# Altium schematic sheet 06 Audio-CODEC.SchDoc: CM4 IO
size 297 x 209 mm; Page Create Date: March  8, 1995; Page Number: 6; Page Size: A4; Comment: radxa_1010; Page Count: 19; RevCode: V1.10; Doc: 06 Audio-CODEC; DsnPath: D:\WMS\黄工\[RC126]CM4_IO_V1.10\[RC126]_V1.10\CM4 IO_V1.10.DSN; SchematicName: CM4 IO V1.10; PageName: 06 Audio-CODEC; PageSize: A4; TopSchematic: True
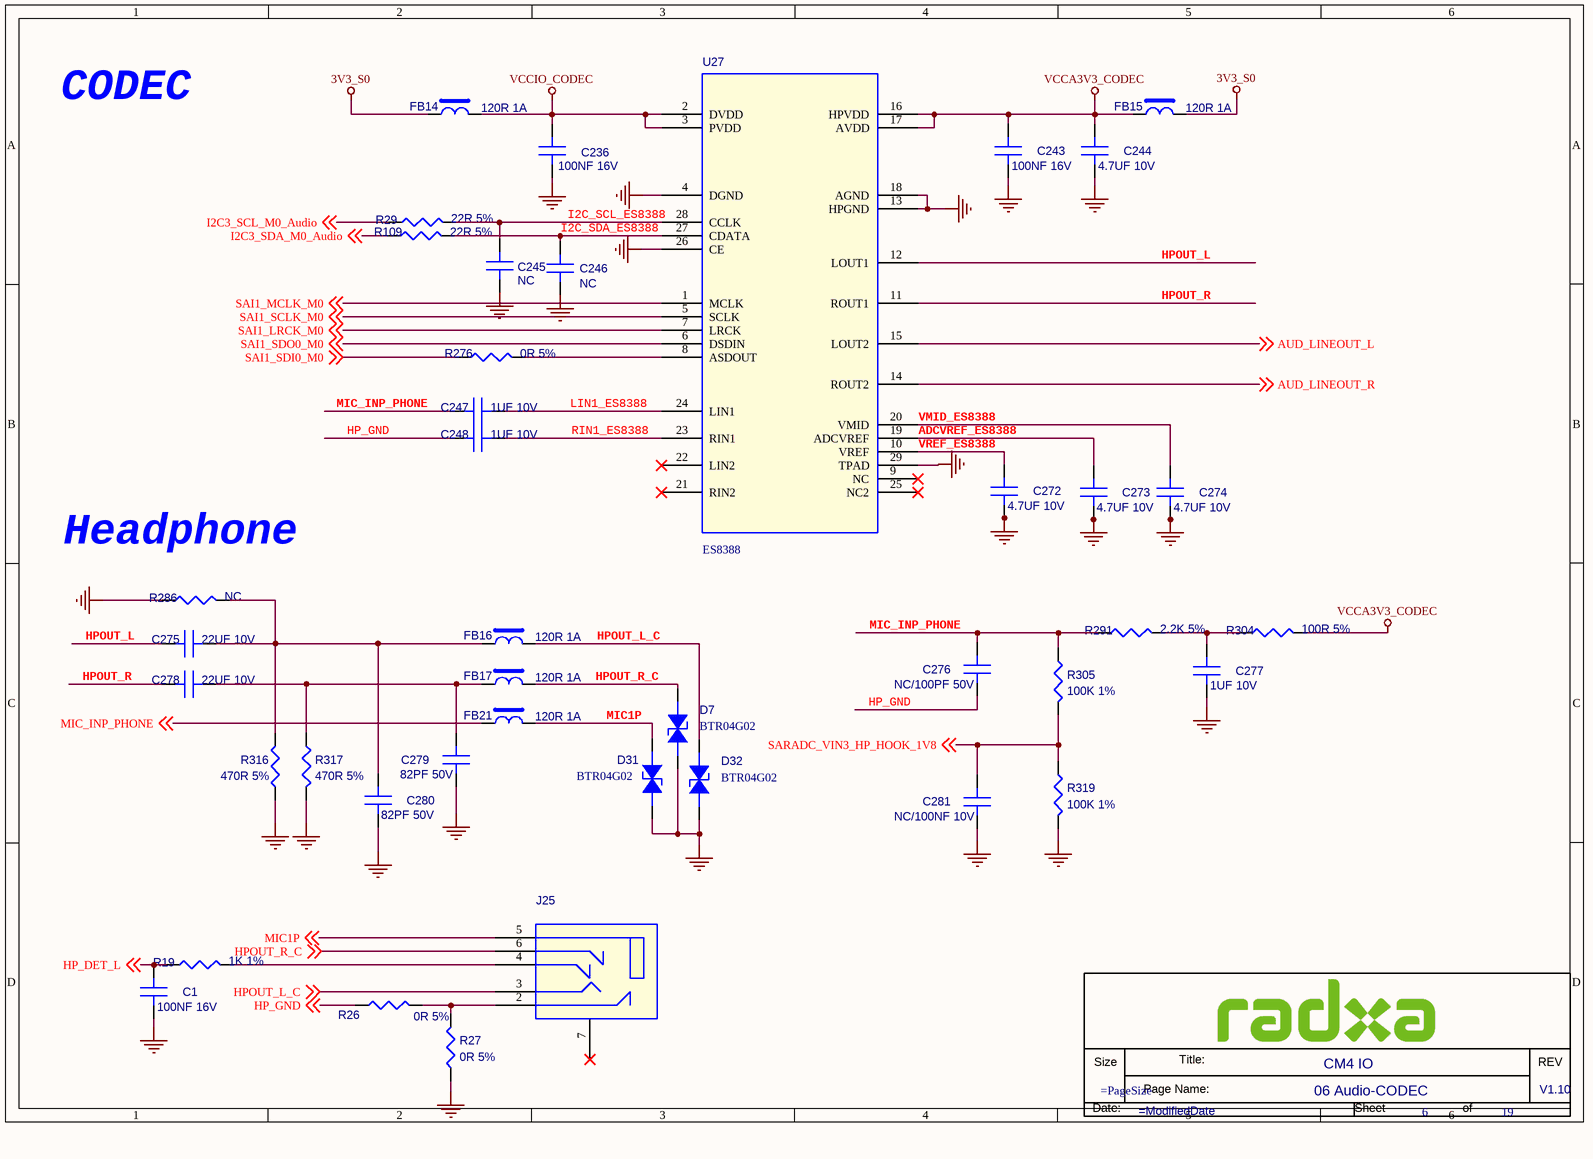
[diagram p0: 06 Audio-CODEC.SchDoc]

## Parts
*  Doc: 06 Audio-CODEC  RevCode: V1.10  Title: CM4 IO  Page Number: 6  Page Count: 19  (hidden comment: radxa_1010)  (graphical)
C1  100NF 16V  [C0201]
C236  100NF 16V  [C0201]
C243  100NF 16V  [C0201]
C244  4.7UF 10V  [C0402]
C245  NC  [C0201]
C246  NC  [C0201]
C247  1UF 10V  [C0201]
C248  1UF 10V  [C0201]
C272  4.7UF 10V  [C0402]
C273  4.7UF 10V  [C0402]
C274  4.7UF 10V  [C0402]
C275  22UF 10V  [C0603]
C276  NC/100PF 50V  [C0201]
C277  1UF 10V  [C0201]
C278  22UF 10V  [C0603]
C279  82PF 50V  [C0201]
C280  82PF 50V  [C0201]
C281  NC/100NF 10V  [C0201]
D7  BTR04G02  [DFN1006-2L]
D31  BTR04G02  [DFN1006-2L]
D32  BTR04G02  [DFN1006-2L]
FB14  120R 1A  [FB0201]
FB15  120R 1A  [FB0201]
FB16  120R 1A  [FB0201]
FB17  120R 1A  [FB0201]
FB21  120R 1A  [FB0201]
J25  (no value)  [AUDIO_SM6_LIE]
R19  1K 1%  [R0402]
R26  0R 5%  [R0402]
R27  0R 5%  [R0402]
R29  22R 5%  [R0402]
R109  22R 5%  [R0402]
R276  0R 5%  [R0402]
R286  NC  [R0402]
R291  2.2K 5%  [R0402]
R304  100R 5%  [R0402]
R305  100K 1%  [R0402]
R316  470R 5%  [R0402]
R317  470R 5%  [R0402]
R319  100K 1%  [R0402]
U27  ES8388  [QFN28_4X4]

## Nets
3V3_S0: FB14.1 FB15.1
GND: C1.2(B) C236.2(B) C243.2(B) C244.2(B) C245.2(B) C246.2(B) C272.2(B) C273.2(B) C274.2(B) C277.2(B) C279.2(B) C280.2(B) C281.2(B) D7.2(CATHODE) D31.2(CATHODE) D32.2(CATHODE) R27.1 R286.1 R316.2 R317.2 R319.2 U27.4(DGND) U27.13(HPGND) U27.18(AGND) U27.26(CE) U27.29(TPAD)
VCCA3V3_CODEC: C243.1(A) C244.1(A) FB15.2 R304.2 U27.16(HPVDD) U27.17(AVDD)
VCCIO_CODEC: C236.1(A) FB14.2 U27.2(DVDD) U27.3(PVDD)
ADCVREF_ES8388: C273.1(A) U27.19(ADCVREF)
AUD_LINEOUT_L: U27.15(LOUT2) ; off-sheet AUD_LINEOUT_L
AUD_LINEOUT_R: U27.14(ROUT2) ; off-sheet AUD_LINEOUT_R
HP_DET_L: C1.1(A) R19.1 ; off-sheet HP_DET_L
HP_GND: C248.2(B) C276.2(B) R26.1 ; off-sheet HP_GND
HPOUT_L: C275.1(A) U27.12(LOUT1)
HPOUT_L_C: D32.1(ANODE) FB16.2 J25.3(R) ; off-sheet HPOUT_L_C
HPOUT_R: C278.1(A) U27.11(ROUT1)
HPOUT_R_C: D7.1(ANODE) FB17.2 J25.6(HP) ; off-sheet HPOUT_R_C
I2C3_SCL_M0_Audio: R29.1 ; off-sheet I2C3_SCL_M0_Audio
I2C3_SDA_M0_Audio: R109.1 ; off-sheet I2C3_SDA_M0_Audio
I2C_SCL_ES8388: C245.1(A) R29.2 U27.28(CCLK)
I2C_SDA_ES8388: C246.1(A) R109.2 U27.27(CDATA)
LIN1_ES8388: C247.1(A) U27.24(LIN1)
MIC1P: D31.1(ANODE) FB21.2 J25.5(D) ; off-sheet MIC1P
MIC_INP_PHONE: C247.2(B) C276.1(A) FB21.1 R291.1 R305.1 ; off-sheet MIC_INP_PHONE
RIN1_ES8388: C248.1(A) U27.23(RIN1)
SAI1_LRCK_M0: U27.7(LRCK) ; off-sheet SAI1_LRCK_M0
SAI1_MCLK_M0: U27.1(MCLK) ; off-sheet SAI1_MCLK_M0
SAI1_SCLK_M0: U27.5(SCLK) ; off-sheet SAI1_SCLK_M0
SAI1_SDI0_M0: R276.1 ; off-sheet SAI1_SDI0_M0
SAI1_SDO0_M0: U27.6(DSDIN) ; off-sheet SAI1_SDO0_M0
SARADC_VIN3_HP_HOOK_1V8: C281.1(A) R305.2 R319.1 ; off-sheet SARADC_VIN3_HP_HOOK_1V8
VMID_ES8388: C274.1(A) U27.20(VMID)
VREF_ES8388: C272.1(A) U27.10(VREF)
NetC275_2: C275.2(B) C280.1(A) FB16.1 R286.2 R316.1
NetC277_1: C277.1(A) R291.2 R304.1
NetC278_2: C278.2(B) C279.1(A) FB17.1 R317.1
NetJ25_2: J25.2(DH) R26.2 R27.2
NetJ25_4: J25.4(L) R19.2
NetR276_2: R276.2 U27.8(ASDOUT)

Not connected (* = marked no-connect by the designer): J25 7(NC2)*; U27 9(NC)* 21(RIN2)* 22(LIN2)* 25(NC2)*

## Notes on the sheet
- CODEC
- (near R286) Headphone

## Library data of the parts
C1 = C: SMD  0201  100NF  16V  X5R  ±20%  ROHS; PARTS: 1; Part Reference: C1; Part Number: A1C01.00099; OriginalSymbolOrigin: (0,30); PKG_TYPE: CAP2-100-250; LEVEL: STD; PINSWAP: (A,B); Preferred: 6715f349cd0bc5
C236 = C: SMD  0201  100NF  16V  X5R  ±20%  ROHS; PARTS: 1; Part Reference: C236; Part Number: A1C01.00099; OriginalSymbolOrigin: (0,30); PKG_TYPE: CAP2-100-250; LEVEL: STD; PINSWAP: (A,B); Preferred: 6715f349cd0bc5
C243 = C: SMD  0201  100NF  16V  X5R  ±20%  ROHS; PARTS: 1; Part Reference: C243; Part Number: A1C01.00099; OriginalSymbolOrigin: (0,30); PKG_TYPE: CAP2-100-250; LEVEL: STD; PINSWAP: (A,B); Preferred: 6715f349cd0bc5
C244 = C: SMD  0402  4.7UF  10V  X5R  ±20%  ROHS; PARTS: 1; Part Reference: C244; Part Number: A1C01.00073; OriginalSymbolOrigin: (0,30); PKG_TYPE: CAP2-100-250; LEVEL: STD; PINSWAP: (A,B)
C245 = C: SMD  0201  10PF  50V  NPO  ±5%  ROHS; PARTS: 1; Part Reference: C245; Part Number: A1C01.00141; OriginalSymbolOrigin: (0,30); PKG_TYPE: CAP2-100-250; LEVEL: STD; PINSWAP: (A,B)
C246 = C: SMD  0201  10PF  50V  NPO  ±5%  ROHS; PARTS: 1; Part Reference: C246; Part Number: A1C01.00141; OriginalSymbolOrigin: (0,30); PKG_TYPE: CAP2-100-250; LEVEL: STD; PINSWAP: (A,B)
C247 = C: SMD  0201  1UF  10V  X5R  ±20%  ROHS; PARTS: 1; Part Reference: C247; Part Number: A1C01.00081; OriginalSymbolOrigin: (0,30); PKG_TYPE: CAP2-100-250; LEVEL: STD; PINSWAP: (A,B)
C248 = C: SMD  0201  1UF  10V  X5R  ±20%  ROHS; PARTS: 1; Part Reference: C248; Part Number: A1C01.00081; OriginalSymbolOrigin: (0,30); PKG_TYPE: CAP2-100-250; LEVEL: STD; PINSWAP: (A,B)
C272 = C: SMD  0402  4.7UF  10V  X5R  ±20%  ROHS; PARTS: 1; Part Reference: C272; Part Number: A1C01.00073; OriginalSymbolOrigin: (0,30); PKG_TYPE: CAP2-100-250; LEVEL: STD; PINSWAP: (A,B)
C273 = C: SMD  0402  4.7UF  10V  X5R  ±20%  ROHS; PARTS: 1; Part Reference: C273; Part Number: A1C01.00073; OriginalSymbolOrigin: (0,30); PKG_TYPE: CAP2-100-250; LEVEL: STD; PINSWAP: (A,B)
C274 = C: SMD  0402  4.7UF  10V  X5R  ±20%  ROHS; PARTS: 1; Part Reference: C274; Part Number: A1C01.00073; OriginalSymbolOrigin: (0,30); PKG_TYPE: CAP2-100-250; LEVEL: STD; PINSWAP: (A,B)
C275 = C: SMD  0603  22UF  10V  X5R  ±20%  ROHS; PARTS: 1; Part Reference: C275; Part Number: A1C01.00015; OriginalSymbolOrigin: (0,30); PKG_TYPE: CAP2-100-250; LEVEL: STD; PINSWAP: (A,B); Preferred: 6715f349cd0bc5
C276 = C: SMD  0201  100PF  50V  NPO  ±5%  ROHS; PARTS: 1; Part Reference: C276; Part Number: A1C01.00382; OriginalSymbolOrigin: (0,30); PKG_TYPE: CAP2-100-250; LEVEL: STD; PINSWAP: (A,B)
C277 = C: SMD  0201  1UF  10V  X5R  ±20%  ROHS; PARTS: 1; Part Reference: C277; Part Number: A1C01.00081; OriginalSymbolOrigin: (0,30); PKG_TYPE: CAP2-100-250; LEVEL: STD; PINSWAP: (A,B)
C278 = C: SMD  0603  22UF  10V  X5R  ±20%  ROHS; PARTS: 1; Part Reference: C278; Part Number: A1C01.00015; OriginalSymbolOrigin: (0,30); PKG_TYPE: CAP2-100-250; LEVEL: STD; PINSWAP: (A,B); Preferred: 6715f349cd0bc5
C279 = C: SMD  0201  82PF  50V  COG  ±2%  ROHS; PARTS: 1; Part Reference: C279; Part Number: A1C01.00327; OriginalSymbolOrigin: (0,30); PKG_TYPE: CAP2-100-250; LEVEL: STD; PINSWAP: (A,B)
C280 = C: SMD  0201  82PF  50V  COG  ±2%  ROHS; PARTS: 1; Part Reference: C280; Part Number: A1C01.00327; OriginalSymbolOrigin: (0,30); PKG_TYPE: CAP2-100-250; LEVEL: STD; PINSWAP: (A,B)
C281 = C: SMD  0201  100NF  10V  X5R  ±20%  ROHS; PARTS: 1; Part Reference: C281; Part Number: A1C01.00009; OriginalSymbolOrigin: (0,30); PKG_TYPE: CAP2-100-250; LEVEL: STD; PINSWAP: (A,B)
D7 = ESD: SMD  编带  0402  BTR04G02  B-tron  ROHS; Part Reference: D7; Part Number: A1D02.00002; Parameter: ESD-台舟 ESD5341N-封装 esd0402; ID: DE-E0004; PCB Footprint: ESD_D0402; Temp Coeff: -50℃ ~ +125℃
D31 = ESD: SMD  编带  0402  BTR04G02  B-tron  ROHS; Part Reference: D31; Part Number: A1D02.00002; Parameter: ESD-台舟 ESD5341N-封装 esd0402; ID: DE-E0004; PCB Footprint: ESD_D0402; Temp Coeff: -50℃ ~ +125℃
D32 = ESD: SMD  编带  0402  BTR04G02  B-tron  ROHS; Part Reference: D32; Part Number: A1D02.00002; Parameter: ESD-台舟 ESD5341N-封装 esd0402; ID: DE-E0004; PCB Footprint: ESD_D0402; Temp Coeff: -50℃ ~ +125℃
FB14 = BEAD: SMD  0201  FB120R  1A  MPZ0603S121HT000  ±25%  ROHS; Part Reference: FB14; Part Number: A1L09.00033
FB15 = BEAD: SMD  0201  FB120R  1A  MPZ0603S121HT000  ±25%  ROHS; Part Reference: FB15; Part Number: A1L09.00033
FB16 = BEAD: SMD  0201  FB120R  1A  MPZ0603S121HT000  ±25%  ROHS; Part Reference: FB16; Part Number: A1L09.00033
FB17 = BEAD: SMD  0201  FB120R  1A  MPZ0603S121HT000  ±25%  ROHS; Part Reference: FB17; Part Number: A1L09.00033
FB21 = BEAD: SMD  0201  FB120R  1A  MPZ0603S121HT000  ±25%  ROHS; Part Reference: FB21; Part Number: A1L09.00033
J25 = PJ342B: SMD  XJ-DR-PJ342B-00  6PIN  外孔Φ6.0mm  内孔Φ3.6mm  前插后贴  14*6.4*H4.5MM  黑色  镀金铜头   协佳  ROHS; Part Reference: J25; Part Number: A1J10.00001
R19 = R: SMD  0201  1K  1/20W  ±1%  ROHS; Part Reference: R19; Part Number: A1R01.00111; PCB Footprint: R0201; Preferred: 6715f349cd0bc5
R26 = R: SMD  0201  0R  1/20W  ±5%  ROHS; Part Reference: R26; Part Number: A1R01.00027; PCB Footprint: R0201; Temp Coeff: －55℃ ~ ＋125℃
R27 = R: SMD  0201  0R  1/20W  ±5%  ROHS; Part Reference: R27; Part Number: A1R01.00027; PCB Footprint: R0201; Temp Coeff: －55℃ ~ ＋125℃
R29 = R: SMD  0201  22R  1/20W  ±5%  ROHS; Part Reference: R29; Part Number: A1R01.00024; PCB Footprint: R0201
R109 = R: SMD  0201  22R  1/20W  ±5%  ROHS; Part Reference: R109; Part Number: A1R01.00024; PCB Footprint: R0201
R276 = R: SMD  0201  0R  1/20W  ±5%  ROHS; Part Reference: R276; Part Number: A1R01.00027; PCB Footprint: R0201; Temp Coeff: －55℃ ~ ＋125℃
R286 = R: SMD  0201  10K  1/20W  ±5%  ROHS; Part Reference: R286; Part Number: A1R01.00012; PCB Footprint: R0201; Temp Coeff: －55℃ ~ ＋125℃
R291 = R: SMD  0201  2.2K  1/20W  ±5%  ROHS; Part Reference: R291; Part Number: A1R01.00016; PCB Footprint: R0201; Temp Coeff: －55℃ ~ ＋125℃
R304 = R: SMD  0201  100R  1/20W  ±5%  ROHS; Part Reference: R304; Part Number: A1R01.00023; PCB Footprint: R0201; Temp Coeff: －55℃ ~ ＋125℃
R305 = R: SMD  0201  100K  1/20W  ±1%  ROHS; Part Reference: R305; Part Number: A1R01.00165; Preferred: 6715f349cd0bc5
R316 = R: SMD  0201  470R  1/20W  ±5%  ROHS; Part Reference: R316; Part Number: A1R01.00020; PCB Footprint: R0201
R317 = R: SMD  0201  470R  1/20W  ±5%  ROHS; Part Reference: R317; Part Number: A1R01.00020; PCB Footprint: R0201
R319 = R: SMD  0201  100K  1/20W  ±1%  ROHS; Part Reference: R319; Part Number: A1R01.00165; Preferred: 6715f349cd0bc5
U27 = ES8388: SMD  ADC/DAC-专用型  ES8388  QFN28  Everest-semi(顺芯)  ROHS; Part Reference: U27; Part Number: A1I01.00762; PCB Footprint: QFN28_0D45_4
